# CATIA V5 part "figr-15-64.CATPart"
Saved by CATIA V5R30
Part number: Part1
Bounding box of the stored display mesh (mm): x -10 to 10, y -10 to 10, z 0 to 26
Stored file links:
  D:\PROJECTS\CATIA V56R 2020\Resources\Parts File\c15_catia_v5_6r2020_prt\figr-15-64.CATPart
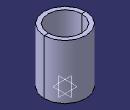
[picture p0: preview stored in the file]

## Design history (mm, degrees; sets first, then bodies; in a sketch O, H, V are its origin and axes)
SheetMetalParameters1: Thickness 2, BendRadius 4, KFactor 0.400515 {= log(min(100,max(20*SheetMetalParameters1.BendRadius,SheetMetalParameters1.Thickness)/SheetMetalParameters1.Thickness))/log(100)/2}, ReliefRadialLength 1, ReliefAxialLength 2, MinimumBendRadius 0
Body1 (main body)
  Sketch1 on xy-plane, origin (0, 0, 0), H (1, 0, 0), V (0, 1, 0)
    circle A1 centre (0, 0) radius 10
    radius A1 = 10
  d_RolledWall1: Extrude_Thickness 2, Extrude_Profile Sketch1, Extrude_StartLength 26, KFacteur 0.400515 {= SheetMetalParameters1.KFactor}, Extrude_EndLength 0, RolledWall_DeductionTable SheetMetalParameters1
